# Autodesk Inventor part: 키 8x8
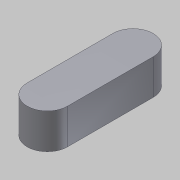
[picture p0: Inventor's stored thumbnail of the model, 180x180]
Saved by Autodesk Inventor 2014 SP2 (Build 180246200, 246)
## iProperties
Company: 한국ATC센터
Created: 2014-10
Part Number: 키 8x8
Document SubType Name: Modeling
Designer: 한국ATC센터
Density: 7.86 g/cm^3
Material: 강, 연강
Mass: 10.2483 g
Surface Area: 7.8646 cm^2
Volume: 1.30386 cm^3
Appearance: 강철
Author: KYOUNG IL JANG
Revision Number: 1
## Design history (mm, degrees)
sketch "스케치1"
  geometry: L1 (28.264, -14)-(28.264, -31) reference; L2 (20.264, -31)-(20.264, -14) reference; A1 r 4 centre (24.264, -31) between (20.264, -31) and (28.264, -31) reference; A2 r 4 centre (24.264, -14) between (28.264, -14) and (20.264, -14) reference; 1 further point
extrude "돌출1" new body sketch "스케치1" distance "d0" = 7; taper "d1" = 0 deg
node "솔리드1"
node "참조1"
